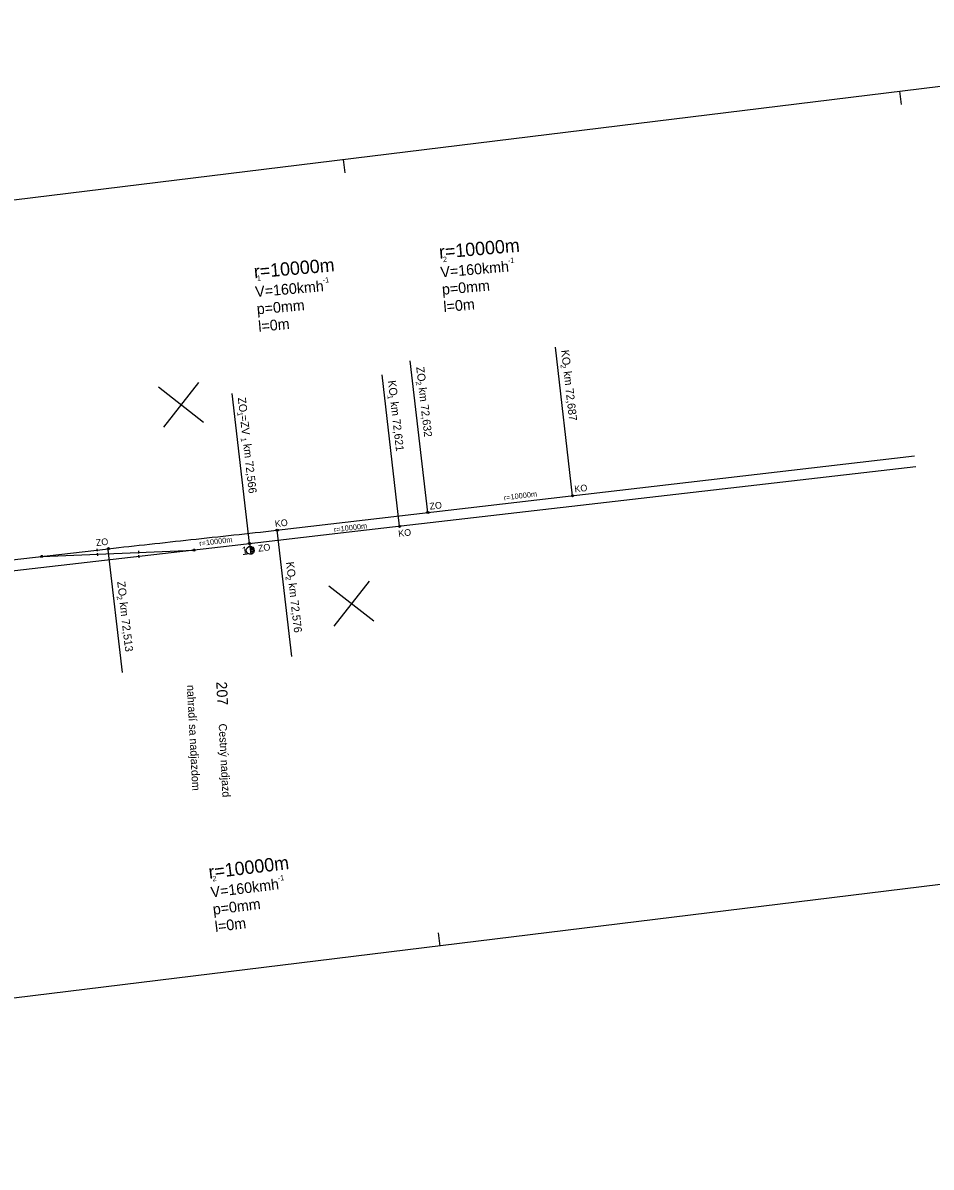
# Model space of a CAD drawing. Extents: x -559083 to -556962, y -1276579 to -1276028.
# Drawn here: x -557535.4 to -557195.2, y -1276456.8 to -1276027.9 of the extents above; entities that cross this region are included whole.
import ezdxf

# ---------------------------------------------------------------- set-up
doc = ezdxf.new("R2010")
doc.units = 0
for name, color, linetype in [('kolaj s', 7, 'Continuous'), ('popis 25', 7, 'Continuous'), ('popis 50', 7, 'Continuous'), ('ram vykresu', 7, 'Continuous'), ('stavby', 7, 'Continuous')]:
    doc.layers.add(name, color=color, linetype=linetype)

msp = doc.modelspace()

# ---------------------------------------------------------------- linework, layer by layer
at = {"layer": 'kolaj s'}
for p, q in [((-557440.36, -1276218.07), (-557201.37, -1276190.23)), ((-557200.9, -1276194.34), (-557413.12, -1276218.79)), ((-557329.45, -1276205.15), (-557329.45, -1276205.15)), ((-557383.7, -1276211.42), (-557383.7, -1276211.42)), ((-557440.15, -1276218.04), (-557440.15, -1276218.04)), ((-557394.26, -1276216.62), (-557394.26, -1276216.62)), ((-557413.12, -1276218.79), (-557457.03, -1276223.86)), ((-557548.94, -1276230.25), (-557503.36, -1276224.98)), ((-557528.28, -1276227.86), (-557471.18, -1276225.5)), ((-557507.68, -1276224.98), (-557507.57, -1276225.97)), ((-557507.62, -1276225.47), (-557507.62, -1276225.47)), ((-557507.51, -1276226.7), (-557507.48, -1276227.7)), ((-557503.32, -1276224.97), (-557503.32, -1276224.97)), ((-557457.03, -1276223.86), (-557498.35, -1276228.64)), ((-557491.95, -1276226.8), (-557491.99, -1276225.8)), ((-557491.97, -1276226.3), (-557491.97, -1276226.3)), ((-557471.18, -1276225.5), (-557471.18, -1276225.5)), ((-557450.52, -1276223.03), (-557450.52, -1276223.03)), ((-557498.35, -1276228.64), (-557565.52, -1276236.4)), ((-557528.28, -1276227.86), (-557528.28, -1276227.86)), ((-557507.5, -1276227.2), (-557507.5, -1276227.2)), ((-557491.78, -1276228.36), (-557491.89, -1276227.37)), ((-557491.83, -1276227.86), (-557491.83, -1276227.86))]:
    msp.add_line(p, q, dxfattribs=at)
for points in [[(-557329.45, -1276205.55), (-557329.79, -1276205.35), (-557329.79, -1276204.96), (-557329.45, -1276204.75), (-557329.1, -1276204.96), (-557329.1, -1276205.35), (-557329.45, -1276205.55)], [(-557383.7, -1276211.82), (-557384.04, -1276211.62), (-557384.04, -1276211.22), (-557383.7, -1276211.02), (-557383.35, -1276211.22), (-557383.35, -1276211.62), (-557383.7, -1276211.82)], [(-557440.15, -1276218.45), (-557440.49, -1276218.25), (-557440.49, -1276217.85), (-557440.15, -1276217.65), (-557439.8, -1276217.85), (-557439.8, -1276218.25), (-557440.15, -1276218.45)], [(-557394.26, -1276217.02), (-557394.6, -1276216.82), (-557394.6, -1276216.42), (-557394.26, -1276216.22), (-557393.91, -1276216.42), (-557393.91, -1276216.82), (-557394.26, -1276217.02)], [(-557503.32, -1276225.37), (-557503.67, -1276225.17), (-557503.67, -1276224.77), (-557503.32, -1276224.57), (-557502.98, -1276224.77), (-557502.98, -1276225.17), (-557503.32, -1276225.37)], [(-557471.58, -1276225.54), (-557471.42, -1276225.18), (-557471.02, -1276225.13), (-557470.78, -1276225.45), (-557470.94, -1276225.82), (-557471.34, -1276225.86), (-557471.58, -1276225.54)], [(-557450.52, -1276223.44), (-557450.86, -1276223.24), (-557450.86, -1276222.84), (-557450.52, -1276222.64), (-557450.17, -1276222.84), (-557450.17, -1276223.24), (-557450.52, -1276223.44)], [(-557527.89, -1276227.82), (-557528.05, -1276228.18), (-557528.44, -1276228.23), (-557528.68, -1276227.91), (-557528.52, -1276227.54), (-557528.12, -1276227.5), (-557527.89, -1276227.82)]]:
    msp.add_lwpolyline(points, dxfattribs=at)
msp.add_spline([(-557503.36, -1276224.98), (-557472.43, -1276221.58), (-557440.36, -1276218.07)], degree=3, dxfattribs=at)
at = {"layer": 'popis 50'}
for p, q in [((-557329.44, -1276205.15), (-557335.87, -1276149.49)), ((-557383.69, -1276211.46), (-557390.26, -1276154.58)), ((-557394.28, -1276216.57), (-557400.84, -1276159.78)), ((-557467.72, -1276177.64), (-557484.56, -1276164.48)), ((-557469.56, -1276162.64), (-557482.72, -1276179.48)), ((-557450.52, -1276222.96), (-557457.01, -1276166.83)), ((-557434.68, -1276265.41), (-557440.14, -1276218.1)), ((-557498.07, -1276271.38), (-557503.38, -1276225.45)), ((-557450.51, -1276223.12), (-557450.51, -1276223.12)), ((-557450.51, -1276223.12), (-557450.03, -1276227.04)), ((-557403.87, -1276252.16), (-557420.72, -1276239)), ((-557405.72, -1276237.16), (-557418.88, -1276254.01))]:
    msp.add_line(p, q, dxfattribs=at)
msp.add_lwpolyline([(-557449.63, -1276227), (-557450.42, -1276227.09), (-557451.15, -1276226.77), (-557451.59, -1276226.18), (-557451.69, -1276225.38), (-557451.39, -1276224.68), (-557450.78, -1276224.21), (-557449.98, -1276224.12), (-557449.28, -1276224.42), (-557448.81, -1276225.04), (-557448.72, -1276225.81), (-557449.02, -1276226.53), (-557449.63, -1276227), (-557449.41, -1276226.72), (-557449.91, -1276226.78), (-557449.94, -1276226.48), (-557449.1, -1276226.38), (-557448.99, -1276226.06), (-557449.98, -1276226.18), (-557450.02, -1276225.88), (-557448.88, -1276225.74), (-557448.91, -1276225.45), (-557450.05, -1276225.59), (-557450.09, -1276225.29), (-557448.95, -1276225.15), (-557449.13, -1276224.87), (-557450.13, -1276224.99), (-557450.16, -1276224.69), (-557449.37, -1276224.59), (-557449.75, -1276224.34), (-557450.2, -1276224.4)], dxfattribs=at)
at = {"layer": 'ram vykresu'}
for p, q in [((-558090.24, -1276161.98), (-556998.42, -1276027.92)), ((-557206.25, -1276058.47), (-557206.85, -1276053.51)), ((-557414.68, -1276084.06), (-557415.29, -1276079.1)), ((-556962.22, -1276322.7), (-558054.04, -1276456.76)), ((-557379.09, -1276373.89), (-557379.7, -1276368.93))]:
    msp.add_line(p, q, dxfattribs=at)

# ---------------------------------------------------------------- texts
at = {"layer": 'popis 25'}
for s, height, rotation, p in [('KO', 2.5, 7, (-557328.61, -1276203.92)), ('r=10000m', 2, 6.8, (-557355.11, -1276206.87)), ('ZO', 2.5, 7, (-557382.89, -1276210.37)), ('KO', 2.5, 7, (-557440.83, -1276216.94)), ('r=10000m', 2, 6.8, (-557418.76, -1276218.83)), ('KO', 2.5, 7, (-557394.61, -1276220.58)), ('ZO', 2.5, 7, (-557507.87, -1276224.04)), ('r=10000m', 2, 6.8, (-557469.2, -1276224.01)), ('ZO', 2.5, 7, (-557447.16, -1276226.14))]:
    msp.add_text(s, height=height, rotation=rotation, dxfattribs=at).set_placement(p)
at = {"layer": 'popis 50'}
for s, height, rotation, p in [('r=10000m', 5, 5, (-557379.27, -1276116.3)), ('r=10000m', 5, 5, (-557448.64, -1276123.66)), ('V=160kmh', 4, 5, (-557378.79, -1276123.35)), ('2', 2, 5, (-557377.96, -1276117.61)), ('-1', 2, 5, (-557353.64, -1276118.01)), ('1', 2, 5, (-557447.66, -1276124.6)), ('-1', 2, 5, (-557423.01, -1276125.37)), ('V=160kmh', 4, 5, (-557448.17, -1276130.71)), ('p=0mm', 4, 5, (-557378.23, -1276129.82)), ('p=0mm', 4, 5, (-557447.6, -1276137.18)), ('l=0m', 4, 5, (-557377.66, -1276136.3)), ('l=0m', 4, 5, (-557447.03, -1276143.66)), ('KO  km 72,687', 3, 276.5918, (-557333.79, -1276150.64)), ('ZO  km 72,632', 3, 276.5918, (-557388.04, -1276156.95)), ('2', 2, 276.5918, (-557333.99, -1276156.06)), ('KO  km 72,621', 3, 276.5918, (-557398.63, -1276162.06)), ('2', 2, 276.5918, (-557388.24, -1276162.36)), ('ZO =ZV   km 72,566', 3, 276.5918, (-557454.87, -1276168.45)), ('1', 2, 276.5918, (-557398.83, -1276167.48)), ('1', 2, 276.5918, (-557455.08, -1276173.86)), ('1', 2, 276.5918, (-557453.8, -1276183.52)), ('1', 3, 7, (-557453.18, -1276227.39)), ('KO  km 72,576', 3, 276.5918, (-557436.81, -1276230.04)), ('2', 2, 276.5918, (-557437.02, -1276235.46)), ('ZO  km 72,513', 3, 276.5918, (-557500.05, -1276237.39)), ('2', 2, 276.5918, (-557500.26, -1276242.81)), ('r=10000m', 5, 7, (-557465.52, -1276348.71)), ('V=160kmh', 4, 7, (-557464.79, -1276355.73)), ('2', 2, 7, (-557464.28, -1276349.7)), ('-1', 2, 7, (-557439.84, -1276349.52)), ('p=0mm', 4, 7, (-557464, -1276362.19)), ('l=0m', 4, 7, (-557463.21, -1276368.64))]:
    msp.add_text(s, height=height, rotation=rotation, dxfattribs=at).set_placement(p)
at = {"layer": 'stavby'}
for s, height, p in [('nahradí sa nadjazdom', 3, (-557473.97, -1276276.12)), ('207', 4, (-557462.96, -1276274.89)), ('Cestný nadjazd', 3, (-557462.04, -1276290.6))]:
    msp.add_text(s, height=height, rotation=273, dxfattribs=at).set_placement(p)

doc.saveas('drawing.dxf')
